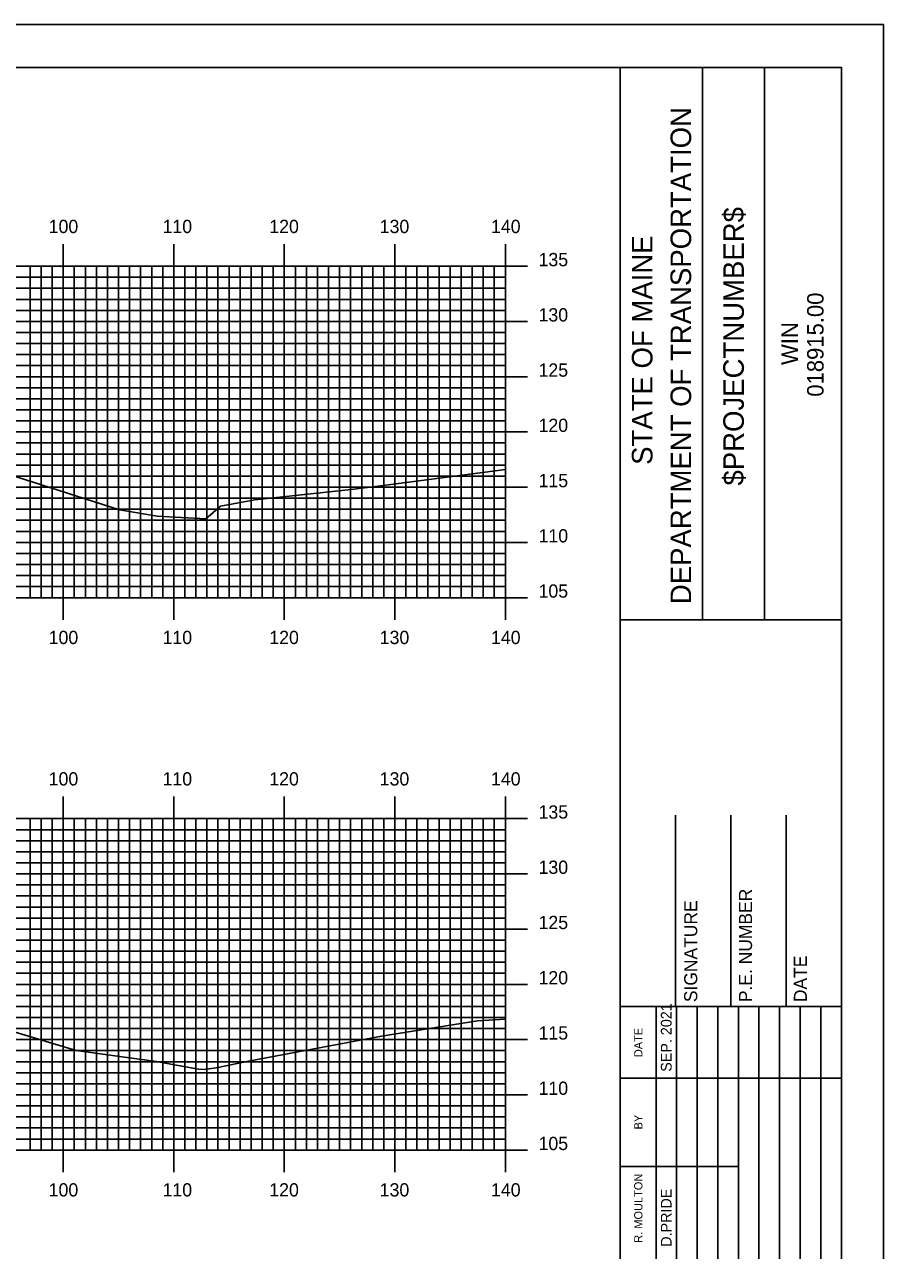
# Model space of a CAD drawing. Extents: x 854681 to 855024, y 366605 to 366825.
# Drawn here: x 854943.1 to 855020.8, y 366714 to 366824.9 of the extents above; entities that cross this region are included whole.
import ezdxf

# ---------------------------------------------------------------- set-up
doc = ezdxf.new("R2010")
doc.units = 0
for name, color, linetype in [('BORDER', 7, 'Continuous'), ('H_V ANNOTATION', 7, 'Continuous'), ('MAJOR', 7, 'Continuous'), ('MINOR', 7, 'Continuous'), ('PLOT BOUNDARY', 7, 'Continuous'), ('S_Roadway_Centerline', 7, 'Continuous')]:
    doc.layers.add(name, color=color, linetype=linetype)

msp = doc.modelspace()

# ---------------------------------------------------------------- linework, layer by layer
at = {"layer": 'BORDER'}
for p, q in [((854996.96, 366611.06), (854996.96, 366821.06)), ((855004.41, 366771.05), (855004.41, 366821.05)), ((855010, 366771.05), (855010, 366821.05)), ((854996.96, 366771.04), (855016.96, 366771.04)), ((855001.96, 366736.06), (855001.96, 366753.36)), ((855006.96, 366736.06), (855006.96, 366753.36)), ((855011.96, 366736.06), (855011.96, 366753.36)), ((854996.96, 366736.06), (855016.96, 366736.06))]:
    msp.add_line(p, q, dxfattribs=at)
msp.add_lwpolyline([(854696.96, 366611.06), (855016.96, 366611.06), (855016.96, 366821.06), (854696.96, 366821.06)], close=True, dxfattribs=at)
for points in [[(855000.19, 366729.56), (855000.19, 366736.06)], [(855002.05, 366701.07), (855002.05, 366736.06)], [(855003.91, 366736.06), (855003.91, 366701.07)], [(855005.78, 366701.07), (855005.78, 366736.06)], [(855007.64, 366701.07), (855007.64, 366736.06)], [(855009.5, 366701.07), (855009.5, 366736.06)], [(855011.37, 366701.07), (855011.37, 366736.06)], [(855013.23, 366701.07), (855013.23, 366736.06)], [(855015.09, 366701.07), (855015.09, 366736.06)], [(855000.19, 366701.07), (855000.19, 366734.65)], [(854996.96, 366729.56), (855016.96, 366729.56)], [(854996.96, 366721.56), (855000.19, 366721.56)], [(855000.19, 366721.56), (855007.64, 366721.56)]]:
    msp.add_lwpolyline(points, dxfattribs=at)
at = {"layer": 'MAJOR'}
for p, q in [((854946.56, 366805.06), (854946.56, 366803.06)), ((854956.56, 366805.06), (854956.56, 366803.06)), ((854966.56, 366805.06), (854966.56, 366803.06)), ((854976.56, 366805.06), (854976.56, 366803.06)), ((854986.56, 366805.06), (854986.56, 366803.06)), ((854706.56, 366803.06), (854986.56, 366803.06)), ((854706.56, 366803.06), (854986.56, 366803.06)), ((854946.56, 366773.06), (854946.56, 366803.06)), ((854956.56, 366773.06), (854956.56, 366803.06)), ((854966.56, 366773.06), (854966.56, 366803.06)), ((854976.56, 366773.06), (854976.56, 366803.06)), ((854988.56, 366803.06), (854984.55, 366803.06)), ((854986.56, 366773.06), (854986.56, 366803.06)), ((854986.56, 366773.06), (854986.56, 366803.06)), ((854706.56, 366798.06), (854986.56, 366798.06)), ((854988.56, 366798.06), (854984.55, 366798.06)), ((854706.56, 366793.06), (854986.56, 366793.06)), ((854988.56, 366793.06), (854984.55, 366793.06)), ((854706.56, 366788.06), (854986.56, 366788.06)), ((854988.56, 366788.06), (854984.55, 366788.06)), ((854706.56, 366783.06), (854986.56, 366783.06)), ((854988.56, 366783.06), (854984.55, 366783.06)), ((854706.56, 366778.06), (854986.56, 366778.06)), ((854988.56, 366778.06), (854984.55, 366778.06)), ((854706.56, 366773.06), (854986.56, 366773.06)), ((854706.56, 366773.06), (854986.56, 366773.06)), ((854946.56, 366771.05), (854946.56, 366773.06)), ((854956.56, 366771.05), (854956.56, 366773.06)), ((854966.56, 366771.05), (854966.56, 366773.06)), ((854976.56, 366771.05), (854976.56, 366773.06)), ((854988.56, 366773.06), (854984.55, 366773.06)), ((854986.56, 366771.05), (854986.56, 366773.06)), ((854946.56, 366755.06), (854946.56, 366753.06)), ((854956.56, 366755.06), (854956.56, 366753.06)), ((854966.56, 366755.06), (854966.56, 366753.06)), ((854976.56, 366755.06), (854976.56, 366753.06)), ((854986.56, 366755.06), (854986.56, 366753.06)), ((854706.56, 366753.06), (854986.56, 366753.06)), ((854706.56, 366753.06), (854986.56, 366753.06)), ((854946.56, 366723.06), (854946.56, 366753.06)), ((854956.56, 366723.06), (854956.56, 366753.06)), ((854966.56, 366723.06), (854966.56, 366753.06)), ((854976.56, 366723.06), (854976.56, 366753.06)), ((854988.56, 366753.06), (854984.55, 366753.06)), ((854986.56, 366723.06), (854986.56, 366753.06)), ((854986.56, 366723.06), (854986.56, 366753.06)), ((854706.56, 366748.06), (854986.56, 366748.06)), ((854988.56, 366748.06), (854984.55, 366748.06)), ((854706.56, 366743.06), (854986.56, 366743.06)), ((854988.56, 366743.06), (854984.55, 366743.06)), ((854706.56, 366738.06), (854986.56, 366738.06)), ((854988.56, 366738.06), (854984.55, 366738.06)), ((854706.56, 366733.06), (854986.56, 366733.06)), ((854988.56, 366733.06), (854984.55, 366733.06)), ((854706.56, 366728.06), (854986.56, 366728.06)), ((854988.56, 366728.06), (854984.55, 366728.06)), ((854706.56, 366723.06), (854986.56, 366723.06)), ((854706.56, 366723.06), (854986.56, 366723.06)), ((854946.56, 366721.05), (854946.56, 366723.06)), ((854956.56, 366721.05), (854956.56, 366723.06)), ((854966.56, 366721.05), (854966.56, 366723.06)), ((854976.56, 366721.05), (854976.56, 366723.06)), ((854988.56, 366723.06), (854984.55, 366723.06)), ((854986.56, 366721.05), (854986.56, 366723.06))]:
    msp.add_line(p, q, dxfattribs=at)
at = {"layer": 'MINOR'}
for p, q in [((854943.56, 366773.06), (854943.56, 366803.06)), ((854944.56, 366773.06), (854944.56, 366803.06)), ((854945.56, 366773.06), (854945.56, 366803.06)), ((854947.56, 366773.06), (854947.56, 366803.06)), ((854948.56, 366773.06), (854948.56, 366803.06)), ((854949.56, 366773.06), (854949.56, 366803.06)), ((854950.56, 366773.06), (854950.56, 366803.06)), ((854951.56, 366773.06), (854951.56, 366803.06)), ((854952.56, 366773.06), (854952.56, 366803.06)), ((854953.56, 366773.06), (854953.56, 366803.06)), ((854954.56, 366773.06), (854954.56, 366803.06)), ((854955.56, 366773.06), (854955.56, 366803.06)), ((854957.56, 366773.06), (854957.56, 366803.06)), ((854958.56, 366773.06), (854958.56, 366803.06)), ((854959.56, 366773.06), (854959.56, 366803.06)), ((854960.56, 366773.06), (854960.56, 366803.06)), ((854961.56, 366773.06), (854961.56, 366803.06)), ((854962.56, 366773.06), (854962.56, 366803.06)), ((854963.56, 366773.06), (854963.56, 366803.06)), ((854964.56, 366773.06), (854964.56, 366803.06)), ((854965.56, 366773.06), (854965.56, 366803.06)), ((854967.56, 366773.06), (854967.56, 366803.06)), ((854968.56, 366773.06), (854968.56, 366803.06)), ((854969.56, 366773.06), (854969.56, 366803.06)), ((854970.56, 366773.06), (854970.56, 366803.06)), ((854971.56, 366773.06), (854971.56, 366803.06)), ((854972.56, 366773.06), (854972.56, 366803.06)), ((854973.56, 366773.06), (854973.56, 366803.06)), ((854974.56, 366773.06), (854974.56, 366803.06)), ((854975.56, 366773.06), (854975.56, 366803.06)), ((854977.56, 366773.06), (854977.56, 366803.06)), ((854978.56, 366773.06), (854978.56, 366803.06)), ((854979.56, 366773.06), (854979.56, 366803.06)), ((854980.56, 366773.06), (854980.56, 366803.06)), ((854981.56, 366773.06), (854981.56, 366803.06)), ((854982.56, 366773.06), (854982.56, 366803.06)), ((854983.56, 366773.06), (854983.56, 366803.06)), ((854984.56, 366773.06), (854984.56, 366803.06)), ((854985.56, 366773.06), (854985.56, 366803.06)), ((854706.56, 366802.06), (854986.56, 366802.06)), ((854986.56, 366802.06), (854984.55, 366802.06)), ((854706.56, 366801.06), (854986.56, 366801.06)), ((854986.56, 366801.06), (854984.55, 366801.06)), ((854706.56, 366800.06), (854986.56, 366800.06)), ((854986.56, 366800.06), (854984.55, 366800.06)), ((854706.56, 366799.06), (854986.56, 366799.06)), ((854986.56, 366799.06), (854984.55, 366799.06)), ((854706.56, 366797.06), (854986.56, 366797.06)), ((854986.56, 366797.06), (854984.55, 366797.06)), ((854706.56, 366796.06), (854986.56, 366796.06)), ((854986.56, 366796.06), (854984.55, 366796.06)), ((854706.56, 366795.06), (854986.56, 366795.06)), ((854986.56, 366795.06), (854984.55, 366795.06)), ((854706.56, 366794.06), (854986.56, 366794.06)), ((854986.56, 366794.06), (854984.55, 366794.06)), ((854706.56, 366792.06), (854986.56, 366792.06)), ((854986.56, 366792.06), (854984.55, 366792.06)), ((854706.56, 366791.06), (854986.56, 366791.06)), ((854986.56, 366791.06), (854984.55, 366791.06)), ((854706.56, 366790.06), (854986.56, 366790.06)), ((854986.56, 366790.06), (854984.55, 366790.06)), ((854706.56, 366789.06), (854986.56, 366789.06)), ((854986.56, 366789.06), (854984.55, 366789.06)), ((854706.56, 366787.06), (854986.56, 366787.06)), ((854986.56, 366787.06), (854984.55, 366787.06)), ((854706.56, 366786.06), (854986.56, 366786.06)), ((854986.56, 366786.06), (854984.55, 366786.06)), ((854706.56, 366785.06), (854986.56, 366785.06)), ((854986.56, 366785.06), (854984.55, 366785.06)), ((854706.56, 366784.06), (854986.56, 366784.06)), ((854986.56, 366784.06), (854984.55, 366784.06)), ((854706.56, 366782.06), (854986.56, 366782.06)), ((854986.56, 366782.06), (854984.55, 366782.06)), ((854706.56, 366781.06), (854986.56, 366781.06)), ((854986.56, 366781.06), (854984.55, 366781.06)), ((854706.56, 366780.06), (854986.56, 366780.06)), ((854986.56, 366780.06), (854984.55, 366780.06)), ((854706.56, 366779.06), (854986.56, 366779.06)), ((854986.56, 366779.06), (854984.55, 366779.06)), ((854706.56, 366777.06), (854986.56, 366777.06)), ((854986.56, 366777.06), (854984.55, 366777.06)), ((854706.56, 366776.06), (854986.56, 366776.06)), ((854986.56, 366776.06), (854984.55, 366776.06)), ((854706.56, 366775.06), (854986.56, 366775.06)), ((854986.56, 366775.06), (854984.55, 366775.06)), ((854706.56, 366774.06), (854986.56, 366774.06)), ((854986.56, 366774.06), (854984.55, 366774.06)), ((854943.56, 366723.06), (854943.56, 366753.06)), ((854944.56, 366723.06), (854944.56, 366753.06)), ((854945.56, 366723.06), (854945.56, 366753.06)), ((854947.56, 366723.06), (854947.56, 366753.06)), ((854948.56, 366723.06), (854948.56, 366753.06)), ((854949.56, 366723.06), (854949.56, 366753.06)), ((854950.56, 366723.06), (854950.56, 366753.06)), ((854951.56, 366723.06), (854951.56, 366753.06)), ((854952.56, 366723.06), (854952.56, 366753.06)), ((854953.56, 366723.06), (854953.56, 366753.06)), ((854954.56, 366723.06), (854954.56, 366753.06)), ((854955.56, 366723.06), (854955.56, 366753.06)), ((854957.56, 366723.06), (854957.56, 366753.06)), ((854958.56, 366723.06), (854958.56, 366753.06)), ((854959.56, 366723.06), (854959.56, 366753.06)), ((854960.56, 366723.06), (854960.56, 366753.06)), ((854961.56, 366723.06), (854961.56, 366753.06)), ((854962.56, 366723.06), (854962.56, 366753.06)), ((854963.56, 366723.06), (854963.56, 366753.06)), ((854964.56, 366723.06), (854964.56, 366753.06)), ((854965.56, 366723.06), (854965.56, 366753.06)), ((854967.56, 366723.06), (854967.56, 366753.06)), ((854968.56, 366723.06), (854968.56, 366753.06)), ((854969.56, 366723.06), (854969.56, 366753.06)), ((854970.56, 366723.06), (854970.56, 366753.06)), ((854971.56, 366723.06), (854971.56, 366753.06)), ((854972.56, 366723.06), (854972.56, 366753.06)), ((854973.56, 366723.06), (854973.56, 366753.06)), ((854974.56, 366723.06), (854974.56, 366753.06)), ((854975.56, 366723.06), (854975.56, 366753.06)), ((854977.56, 366723.06), (854977.56, 366753.06)), ((854978.56, 366723.06), (854978.56, 366753.06)), ((854979.56, 366723.06), (854979.56, 366753.06)), ((854980.56, 366723.06), (854980.56, 366753.06)), ((854981.56, 366723.06), (854981.56, 366753.06)), ((854982.56, 366723.06), (854982.56, 366753.06)), ((854983.56, 366723.06), (854983.56, 366753.06)), ((854984.56, 366723.06), (854984.56, 366753.06)), ((854985.56, 366723.06), (854985.56, 366753.06)), ((854706.56, 366752.06), (854986.56, 366752.06)), ((854986.56, 366752.06), (854984.55, 366752.06)), ((854706.56, 366751.06), (854986.56, 366751.06)), ((854986.56, 366751.06), (854984.55, 366751.06)), ((854706.56, 366750.06), (854986.56, 366750.06)), ((854986.56, 366750.06), (854984.55, 366750.06)), ((854706.56, 366749.06), (854986.56, 366749.06)), ((854986.56, 366749.06), (854984.55, 366749.06)), ((854706.56, 366747.06), (854986.56, 366747.06)), ((854986.56, 366747.06), (854984.55, 366747.06)), ((854706.56, 366746.06), (854986.56, 366746.06)), ((854986.56, 366746.06), (854984.55, 366746.06)), ((854706.56, 366745.06), (854986.56, 366745.06)), ((854986.56, 366745.06), (854984.55, 366745.06)), ((854706.56, 366744.06), (854986.56, 366744.06)), ((854986.56, 366744.06), (854984.55, 366744.06)), ((854706.56, 366742.06), (854986.56, 366742.06)), ((854986.56, 366742.06), (854984.55, 366742.06)), ((854706.56, 366741.06), (854986.56, 366741.06)), ((854986.56, 366741.06), (854984.55, 366741.06)), ((854706.56, 366740.06), (854986.56, 366740.06)), ((854986.56, 366740.06), (854984.55, 366740.06)), ((854706.56, 366739.06), (854986.56, 366739.06)), ((854986.56, 366739.06), (854984.55, 366739.06)), ((854706.56, 366737.06), (854986.56, 366737.06)), ((854986.56, 366737.06), (854984.55, 366737.06)), ((854706.56, 366736.06), (854986.56, 366736.06)), ((854986.56, 366736.06), (854984.55, 366736.06)), ((854706.56, 366735.06), (854986.56, 366735.06)), ((854986.56, 366735.06), (854984.55, 366735.06)), ((854706.56, 366734.06), (854986.56, 366734.06)), ((854986.56, 366734.06), (854984.55, 366734.06)), ((854706.56, 366732.06), (854986.56, 366732.06)), ((854986.56, 366732.06), (854984.55, 366732.06)), ((854706.56, 366731.06), (854986.56, 366731.06)), ((854986.56, 366731.06), (854984.55, 366731.06)), ((854706.56, 366730.06), (854986.56, 366730.06)), ((854986.56, 366730.06), (854984.55, 366730.06)), ((854706.56, 366729.06), (854986.56, 366729.06)), ((854986.56, 366729.06), (854984.55, 366729.06)), ((854706.56, 366727.06), (854986.56, 366727.06)), ((854986.56, 366727.06), (854984.55, 366727.06)), ((854706.56, 366726.06), (854986.56, 366726.06)), ((854986.56, 366726.06), (854984.55, 366726.06)), ((854706.56, 366725.06), (854986.56, 366725.06)), ((854986.56, 366725.06), (854984.55, 366725.06)), ((854706.56, 366724.06), (854986.56, 366724.06)), ((854986.56, 366724.06), (854984.55, 366724.06))]:
    msp.add_line(p, q, dxfattribs=at)
at = {"layer": 'PLOT BOUNDARY'}
msp.add_lwpolyline([(854680.77, 366604.94), (855020.77, 366604.94), (855020.77, 366824.94), (854680.77, 366824.94)], close=True, dxfattribs=at)
at = {"layer": 'S_Roadway_Centerline'}
for points in [[(854940.85, 366784.44), (854943.09, 366783.76), (854951.64, 366781), (854955.06, 366780.45), (854959.47, 366780.19), (854960.79, 366781.34), (854963.88, 366781.91), (854972.6, 366782.85), (854975.06, 366783.14), (854986.56, 366784.66)], [(854942.2, 366733.74), (854947.74, 366732.06), (854954.97, 366731.09), (854958.8, 366730.38), (854959.3, 366730.36), (854960.38, 366730.5), (854963.48, 366731.15), (854975.36, 366733.38), (854984.04, 366734.76), (854986.56, 366734.9)]]:
    msp.add_lwpolyline(points, dxfattribs=at)

# ---------------------------------------------------------------- texts
at = {"layer": 'BORDER'}
for s, height, p in [('DEPARTMENT OF TRANSPORTATION', 1.8635, (855003.37, 366772.47)), ('$PROJECTNUMBER$', 1.8635, (855008.14, 366783.21)), ('STATE OF MAINE', 1.8635, (854999.87, 366785.08)), ('018915.00', 1.491, (855015.35, 366791.25)), ('WIN', 1.491, (855013.03, 366794.12)), ('P.E. NUMBER', 1.1811, (855008.88, 366736.45)), ('SIGNATURE', 1.181, (855003.92, 366736.45)), ('DATE', 1.181, (855013.84, 366736.45)), ('SEP. 2021', 0.969, (855001.6, 366730.15)), ('DATE', 0.743, (854998.96, 366731.47)), ('BY', 0.743, (854998.96, 366724.93)), ('R. MOULTON', 0.745, (854998.96, 366714.67)), ('D.PRIDE', 0.969, (855001.6, 366714.31))]:
    msp.add_text(s, height=height, rotation=90, dxfattribs=at).set_placement(p)
at = {"layer": 'H_V ANNOTATION'}
for s, p in [('100', (854945.24, 366806.06)), ('110', (854955.54, 366806.06)), ('120', (854965.2, 366806.06)), ('130', (854975.19, 366806.06)), ('140', (854985.26, 366806.06)), ('135', (854989.56, 366803.06)), ('130', (854989.56, 366798.06)), ('125', (854989.56, 366793.06)), ('120', (854989.56, 366788.06)), ('115', (854989.56, 366783.06)), ('110', (854989.56, 366778.06)), ('105', (854989.56, 366773.06)), ('100', (854945.24, 366768.86)), ('110', (854955.54, 366768.86)), ('120', (854965.2, 366768.86)), ('130', (854975.19, 366768.86)), ('140', (854985.26, 366768.86)), ('100', (854945.24, 366756.06)), ('110', (854955.54, 366756.06)), ('120', (854965.2, 366756.06)), ('130', (854975.19, 366756.06)), ('140', (854985.26, 366756.06)), ('135', (854989.56, 366753.06)), ('130', (854989.56, 366748.06)), ('125', (854989.56, 366743.06)), ('120', (854989.56, 366738.06)), ('115', (854989.56, 366733.06)), ('110', (854989.56, 366728.06)), ('105', (854989.56, 366723.06)), ('100', (854945.24, 366718.86)), ('110', (854955.54, 366718.86)), ('120', (854965.2, 366718.86)), ('130', (854975.19, 366718.86)), ('140', (854985.26, 366718.86))]:
    msp.add_text(s, height=1.2, dxfattribs=at).set_placement(p)

doc.saveas('drawing.dxf')
